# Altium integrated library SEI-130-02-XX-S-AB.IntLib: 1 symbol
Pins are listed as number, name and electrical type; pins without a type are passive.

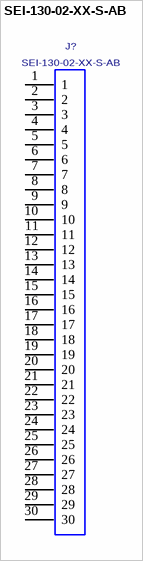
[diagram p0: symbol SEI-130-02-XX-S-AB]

## SEI-130-02-XX-S-AB
designator J?
1mm Single Element Interface; MANUFACTURER: SAMTEC
footprint SEI-130-02-XX-S-AB
pins: 1, 2, 3, 4, 5, 6, 7, 8, 9, 10, 11, 12, 13, 14, 15, 16, 17, 18, 19, 20, 21, 22, 23, 24, 25, 26, 27, 28, 29, 30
